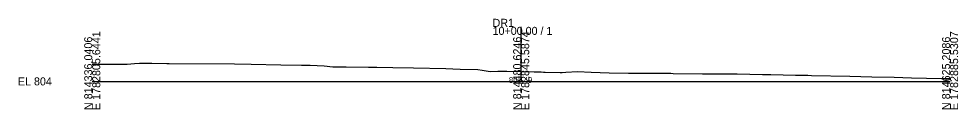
# Model space of a CAD drawing. Extents: x -26 to 303, y -10 to 2017.
# Drawn here: x -25.7 to 302.8, y -9.7 to 21.8 of the extents above; entities that cross this region are included whole.
import ezdxf

# ---------------------------------------------------------------- set-up
doc = ezdxf.new("R2010")
doc.units = 0
for name, color, linetype in [('Exist Cross Section Cell', 7, 'Continuous'), ('Exist XS Center Line Elevation Label', 7, 'Continuous'), ('Exist XS Ground Line', 7, 'Continuous')]:
    doc.layers.add(name, color=color, linetype=linetype)

msp = doc.modelspace()

# ---------------------------------------------------------------- linework, layer by layer
at = {"layer": 'Exist Cross Section Cell'}
for p, q in [((150, 0), (150, 19.03)), ((0, 0), (150, 0)), ((150, 0), (300, 0))]:
    msp.add_line(p, q, dxfattribs=at)
at = {"layer": 'Exist XS Ground Line'}
for p, q in [((0, 5.96), (0.47, 5.96)), ((0.47, 5.96), (8.7, 6.04)), ((8.7, 6.04), (11.3, 6.04)), ((11.3, 6.04), (12.17, 6.06)), ((12.17, 6.06), (14.78, 6.3)), ((14.78, 6.3), (16.47, 6.33)), ((16.47, 6.33), (17.25, 6.34)), ((17.25, 6.34), (19.73, 6.34)), ((19.73, 6.34), (20.78, 6.32)), ((20.78, 6.32), (26.06, 6.28)), ((26.06, 6.28), (26.86, 6.27)), ((26.86, 6.27), (49.8, 6.1)), ((49.8, 6.1), (55.63, 5.96)), ((55.63, 5.96), (65.99, 5.8)), ((65.99, 5.8), (73.23, 5.71)), ((73.23, 5.71), (73.87, 5.71)), ((73.87, 5.71), (74.39, 5.7)), ((74.39, 5.7), (76.25, 5.61)), ((76.25, 5.61), (81.07, 5.4)), ((81.07, 5.4), (84.18, 5.13)), ((84.18, 5.13), (88.74, 5.08)), ((88.74, 5.08), (96.59, 4.99)), ((96.59, 4.99), (99.52, 4.96)), ((99.52, 4.96), (105.1, 4.86)), ((105.1, 4.86), (112.37, 4.75)), ((112.37, 4.75), (123.62, 4.45)), ((123.62, 4.45), (126.13, 4.39)), ((126.13, 4.39), (128.68, 4.31)), ((128.68, 4.31), (134.87, 4.11)), ((134.87, 4.11), (136.39, 3.88)), ((136.39, 3.88), (139.16, 3.48)), ((139.16, 3.48), (141.82, 3.51)), ((141.82, 3.51), (142.85, 3.52)), ((142.85, 3.52), (144.94, 3.52)), ((144.94, 3.52), (150.13, 3.49)), ((150.13, 3.49), (154.56, 3.35)), ((154.56, 3.35), (156.99, 3.33)), ((156.99, 3.33), (157.86, 3.26)), ((165.57, 3.18), (169.72, 3.44)), ((169.72, 3.44), (174.51, 3.2)), ((157.86, 3.26), (158.43, 3.2)), ((158.43, 3.2), (163.65, 3.13)), ((163.65, 3.13), (164.31, 3.12)), ((164.31, 3.12), (165.57, 3.18)), ((174.51, 3.2), (180.81, 2.94)), ((180.81, 2.94), (187.51, 2.91)), ((187.51, 2.91), (189.64, 2.91)), ((189.64, 2.91), (195.81, 2.87)), ((195.81, 2.87), (202.34, 2.82)), ((202.34, 2.82), (203.12, 2.8)), ((203.12, 2.8), (213.42, 2.69)), ((213.42, 2.69), (218.03, 2.65)), ((218.03, 2.65), (225.59, 2.6)), ((225.59, 2.6), (234.38, 2.43)), ((234.38, 2.43), (237.32, 2.36)), ((237.32, 2.36), (245.95, 2.21)), ((245.95, 2.21), (249.3, 2.16)), ((249.3, 2.16), (250.22, 2.13)), ((250.22, 2.13), (251.5, 2.1)), ((251.5, 2.1), (264.93, 1.8)), ((264.93, 1.8), (272.59, 1.54)), ((272.59, 1.54), (280.48, 1.43)), ((280.48, 1.43), (286.46, 1.21)), ((286.46, 1.21), (296.99, 1.03)), ((296.99, 1.03), (300, 0.98))]:
    msp.add_line(p, q, dxfattribs=at)

# ---------------------------------------------------------------- texts
at = {"layer": 'Exist Cross Section Cell'}
for s, p in [('DR1', (140, 19.03)), ('10+00.00 / 1', (140, 16.23)), ('EL 804', (-26, -1.4))]:
    msp.add_text(s, height=2.8, dxfattribs=at).set_placement(p)
for s, p in [('E 1782805.6441', (2.8, -10)), ('E 1782845.5874', (152.8, -10)), ('E 1782885.5307', (302.8, -10)), ('N 814336.0406', (0, -10)), ('N 814480.6246', (150, -10)), ('N 814625.2086', (300, -10))]:
    msp.add_text(s, height=2.8, rotation=90, dxfattribs=at).set_placement(p)
at = {"layer": 'Exist XS Center Line Elevation Label'}
msp.add_text('807.49', height=2, dxfattribs=at).set_placement((145.73, -0.51))

doc.saveas('drawing.dxf')
